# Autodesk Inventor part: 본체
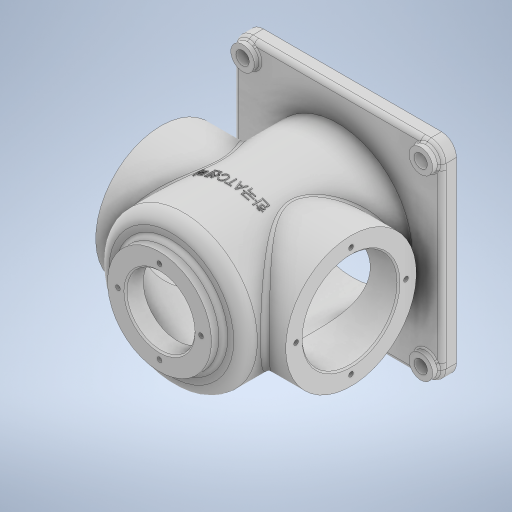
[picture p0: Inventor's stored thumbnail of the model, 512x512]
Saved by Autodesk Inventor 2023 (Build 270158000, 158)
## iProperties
Created: 2025-05
Part Number: 본체
Material: 일반
Document SubType Name: Modeling
Designer: Admin
Density: 1 g/cm^3
Appearance: 기본값
Author: Admin
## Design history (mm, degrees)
sketch "스케치1"
  geometry: L1 (-98, 0)-(98, 0) reference; L2 (0, -98)-(0, 98) reference; L3 (-70, -70)-(70, -70); L4 (70, -70)-(70, 70); L5 (70, 70)-(-70, 70); L6 (-70, 70)-(-70, -70); L7 (-70, -70)-(70, 70); L8 (70, -70)-(-70, 70); 1 further point
  constraints: 12 end point, 2 midpoint, 2 parallel, 1 horizontal, 1 perpendicular
  dimensions: "d0" = 140 distance of L4.end L5.end; "d1" = 140 distance of L3.end L4.end
extrude "돌출1" new body sketch "스케치1" distance "d2" = 10; taper "d3" = 0 deg
sketch "스케치2"
  geometry: L1 (-98, 0)-(98, 0) reference; L2 (0, -98)-(0, 98) reference; C1 r 50 at (0, 0); 1 further point
  constraints: 1 centre point, 1 coincident
  dimensions: "d4" = 100 diameter of C1
extrude "돌출2" join sketch "스케치2" distance "d5" = 112; taper "d6" = 0 deg
sketch "스케치3"
  geometry: L1 (-98, 0)-(98, 0) reference; L2 (0, -98)-(0, 98) reference; C1 r 35 at (0, 0); 1 further point
  constraints: 1 centre point, 1 coincident
  dimensions: "d7" = 70 diameter of C1
extrude "돌출3" join sketch "스케치3" distance "d8" = 8; taper "d9" = 0 deg
node "작업 평면1"
sketch "스케치4"
  geometry: L1 (-98, 0)-(98, 0) reference; L2 (0, -26)-(0, 156) reference; L3 (-70, 0)-(70, 0) reference; C1 r 44 at (0, 65); 2 further points
  constraints: 2 midpoint, 1 centre point
  dimensions: "d11" = 88 diameter of C1; "d12" = 65 distance of point (0, 0) C1.centre
extrude "돌출4" join sketch "스케치4" stored distance "d13" = 8; taper "d14" = 0 deg
sketch "스케치5" dims "d15" = 56
  geometry: L1 (-98, 0)-(98, 0) reference; L2 (0, -98)-(0, 98) reference; 3 further points
  constraints: 1 coincident, 1 horizontal alignment, 1 point on line, 2 other
hole "구멍1" sketch "스케치5" at (-28, 0) diameter "d16" = 3.242; stored, may be unused: countersink angle "d20" = 90 deg, drill point angle "d22" = 118 deg; dims "d17" = 8, "d18" = 4, "d19" = 2, "d21" = 10
sketch "스케치6" dims "d26" = 74
  geometry: L1 (65, -98)-(65, 98) reference; L2 (91, 0)-(-91, 0) reference; L3 (65, -70)-(65, 70) reference; 4 further points
  constraints: 2 midpoint, 1 horizontal alignment, 1 point on line, 2 other
  dimensions: "d27" = 65 distance of point (65, 0) point (0, 0)
hole "구멍2" sketch "스케치6" at (-37, 0) diameter "d28" = 3.242; stored, may be unused: countersink angle "d32" = 90 deg, drill point angle "d34" = 118 deg; dims "d29" = 8, "d30" = 4, "d31" = 2, "d33" = 10
sketch "스케치7"
  geometry: L1 (-98, 0)-(98, 0) reference; L2 (0, -98)-(0, 98) reference; C1 r 35 at (0, 0) reference; C2 r 23 at (0, 0); 1 further point
  constraints: 1 centre point, 1 coincident
  dimensions: "d38" = 46 diameter of C2
extrude "돌출5" cut sketch "스케치7" distance "d39" = 12; taper "d40" = 0 deg
sketch "스케치8"
  geometry: L1 (-70, 0)-(-70, 10) reference; L2 (-70, 10)-(-50, 10) reference; L3 (-50, 10)-(-50, 21) reference; L4 (-50, 21)-(-64, 21) reference; L5 (-64, 21)-(-64, 26.379) reference; L6 (-64, 26.379)-(-54, 26.379) reference; L7 (-54, 26.379)-(-53.026, 28) reference; L8 (-53.026, 28)-(-54, 29.621) reference; L9 (-54, 29.621)-(-64, 29.621) reference; L10 (-64, 29.621)-(-64, 100.379) reference; L11 (-64, 100.379)-(-54, 100.379) reference; L12 (-54, 100.379)-(-53.026, 102) reference; L13 (-53.026, 102)-(-54, 103.621) reference; L14 (-54, 103.621)-(-64, 103.621) reference; L15 (-64, 103.621)-(-64, 109) reference; L16 (-64, 109)-(-50, 109) reference; L17 (-50, 109)-(-50, 122) reference; L18 (-50, 122)-(-35, 122) reference; L19 (-35, 122)-(-35, 130) reference; L20 (-35, 130)-(-29.621, 130) reference; L21 (-29.621, 130)-(-29.621, 120) reference; L22 (-29.621, 120)-(-28, 119.026) reference; L23 (-28, 119.026)-(-26.379, 120) reference; L24 (-26.379, 120)-(-26.379, 130) reference; L25 (-26.379, 130)-(-23, 130) reference; L26 (-23, 130)-(-23, 118) reference; L27 (-23, 118)-(23, 118) reference; L28 (23, 118)-(23, 130) reference; L29 (23, 130)-(26.379, 130) reference; L30 (26.379, 130)-(26.379, 120) reference; L31 (26.379, 120)-(28, 119.026) reference; L32 (28, 119.026)-(29.621, 120) reference; L33 (29.621, 120)-(29.621, 130) reference; L34 (29.621, 130)-(35, 130) reference; L35 (35, 130)-(35, 122) reference; L36 (35, 122)-(50, 122) reference; L37 (50, 122)-(50, 109) reference; L38 (50, 109)-(64, 109) reference; L39 (64, 109)-(64, 103.621) reference; L40 (64, 103.621)-(54, 103.621) reference; L41 (54, 103.621)-(53.026, 102) reference; L42 (53.026, 102)-(54, 100.379) reference; L43 (54, 100.379)-(64, 100.379) reference; L44 (64, 100.379)-(64, 29.621) reference; L45 (64, 29.621)-(54, 29.621) reference; L46 (54, 29.621)-(53.026, 28) reference; L47 (53.026, 28)-(54, 26.379) reference; L48 (54, 26.379)-(64, 26.379) reference; L49 (64, 26.379)-(64, 21) reference; L50 (64, 21)-(50, 21) reference; L51 (50, 21)-(50, 10) reference; L52 (50, 10)-(70, 10) reference; L53 (70, 10)-(70, 0) reference; L54 (70, 0)-(-70, 0) reference; L55 (98, 0)-(-98, 0) reference; L56 (0, -26)-(0, 156) reference; L57 (0, 0)-(-45, 0); L58 (-45, 0)-(-45, 118); L59 (-45, 118)-(0, 118); L60 (0, 118)-(0, 0); 3 further points
  constraints: 8 end point, 2 parallel, 1 horizontal, 1 perpendicular
  dimensions: "d41" = 45 distance of L58.end L59.end; "d42" = 118 distance of L57.end L58.end
revolve "회전1" sketch "스케치8" stored, may be unused: angle "d43" = 90 deg
sketch "스케치9"
  geometry: L1 (65, -98)-(65, 98) reference; L2 (91, 0)-(-91, 0) reference; L3 (65, -70)-(65, 70) reference; C1 r 32 at (0, 0); 2 further points
  constraints: 2 midpoint, 1 centre point
  dimensions: "d44" = 64 diameter of C1; "d45" = 65 distance of point (65, 0) C1.centre
extrude "돌출6" cut sketch "스케치9" extent not by distance; stored distance "d46" = 0; taper "d47" = 0 deg
node "작업 평면2"
sketch "스케치10"
  geometry: L1 (-98, 0)-(98, 0) reference; L2 (0, -98)-(0, 98) reference; L3 (-60, 60)-(60, 60); L4 (60, 60)-(60, -60); L5 (60, -60)-(-60, -60); L6 (-60, -60)-(-60, 60); L7 (-60, 60)-(60, -60); L8 (60, 60)-(-60, -60); C1 r 8 at (-60, -60); C2 r 8 at (60, -60); C3 r 8 at (60, 60); C4 r 8 at (-60, 60); 5 further points
  constraints: 12 end point, 6 coincident, 4 centre point, 2 midpoint, 2 parallel, 2 symmetric about line, 1 horizontal, 1 perpendicular, 2 other
  dimensions: "d50" = 120 distance of L3.end L4.end; "d51" = 120 distance of L4.end L5.end; "d52" = 16 diameter of C1; "d53" = 16 diameter of C2
extrude "돌출7" join sketch "스케치10" extent not by distance; stored distance "d54" = 0; taper "d55" = 0 deg
fillet "모깎기2" dims "d56" = 10
sketch "스케치11"
  geometry: L1 (98, 0)-(-98, 0) reference; L2 (0, -98)-(0, 98) reference; L3 (-60, 60)-(60, 60); L4 (60, 60)-(60, -60); L5 (60, -60)-(-60, -60); L6 (-60, -60)-(-60, 60); L7 (-60, 60)-(60, -60); L8 (60, 60)-(-60, -60); C1 r 8 at (60, 60) reference; C2 r 4.5 at (60, 60); C3 r 4.5 at (-60, 60); C4 r 4.5 at (60, -60); C5 r 4.5 at (-60, -60); 1 further point
  constraints: 12 end point, 4 centre point, 2 coincident, 2 midpoint, 2 parallel, 2 symmetric about line, 1 horizontal, 1 perpendicular, 2 other
  dimensions: "d57" = 120 distance of L3.end L4.end; "d58" = 120 distance of L4.end L5.end; "d59" = 9 diameter of C2; "d60" = 9 diameter of C3
extrude "돌출8" cut sketch "스케치11" distance "d61" = 14; taper "d62" = 0 deg
fillet "모깎기3" dims "d63" = 3
fillet "모깎기4" dims "d64" = 8
fillet "모깎기5" dims "d65" = 3
chamfer "모따기1" distance "d66" = 1; stored, may be unused: second distance "d67" = 2, angle "d68" = 45 deg
chamfer "모따기2" distance "d69" = 1; stored, may be unused: second distance "d70" = 2, angle "d71" = 45 deg
fillet "모깎기6" dims "d72" = 3
chamfer "모따기3" distance "d73" = 1; stored, may be unused: second distance "d74" = 2, angle "d75" = 45 deg
chamfer "모따기4" distance "d76" = 1; stored, may be unused: second distance "d77" = 2, angle "d78" = 45 deg
node "작업 평면3"
sketch "스케치12" dims "d8" = 8, "d9" = 0
  geometry: L1 (98, 0)-(-98, 0) reference; L2 (0, -26)-(0, 156) reference; 2 further points
  constraints: 1 other
  dimensions: "d80" = 80 vertical distance of point (0, 0) point (1.549, 80)
feature "엠보싱1" sketch "스케치12" dims "d81" = 0.5, "d82" = 0
feature "ѱ耀ѳ耀ѵ耀ѷ耀ѹ耀ѻ耀ѽ耀ѿ耀" dims "d0" = 140, "d1" = 140, "d2" = 10, "d3" = 0, "d4" = 100, "d5" = 112, "d6" = 0, "d7" = 70, "d8" = 8, "d9" = 0, "d10" = 64, "d11" = 88, "d12" = 65, "d13" = 8, "d14" = 0, "d15" = 56, "d16" = 3.242, "d17" = 8, "d18" = 4, "d19" = 2, "d20" = 90 deg, "d21" = 10, "d22" = 118 deg, "d23" = 40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
node "솔리드1"
mirror "미러1"
pattern_circular "원형 패턴1" dims angle "d24" = 360 deg
pattern_circular "원형 패턴2" dims angle "d36" = 360 deg
mirror "미러2"
node "절단 모서리 투영1"
feature "A9D066F2-1C7D-4E18-AEED-F7BC21143FA4" dims "d16" = 3.242, "d17" = 8, "d18" = 4, "d19" = 2, "d20" = 90 deg, "d21" = 10, "d22" = 118 deg
